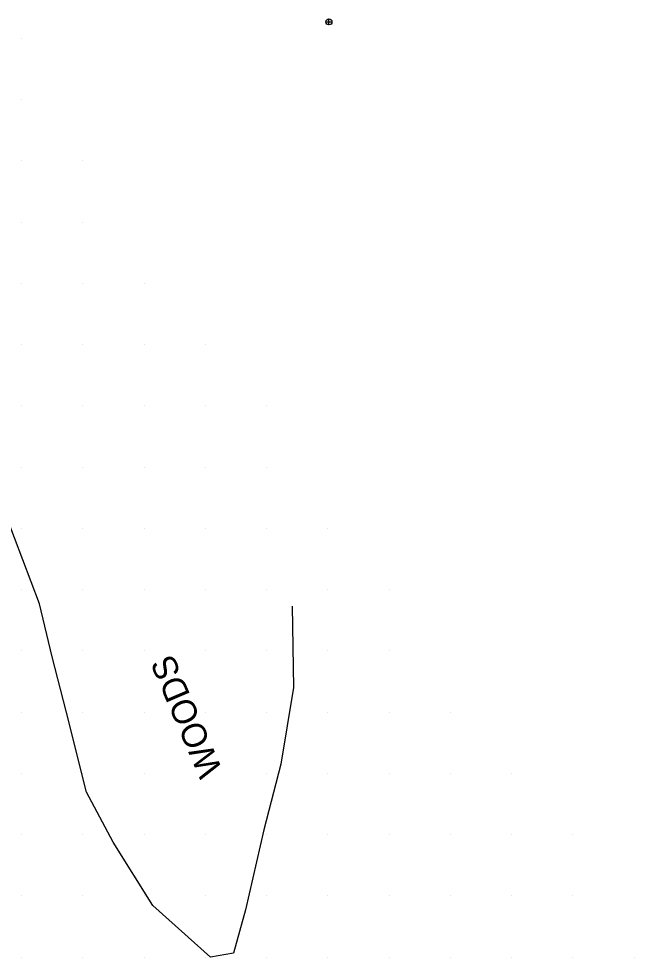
# Model space of a CAD drawing. Extents: x 1548934 to 1561348, y 809680 to 824075.
# Drawn here: x 1552269.6 to 1552370, y 810279.9 to 810433.2 of the extents above; entities that cross this region are included whole.
import ezdxf

# ---------------------------------------------------------------- set-up
doc = ezdxf.new("R2010")
doc.units = 0
for name, color, linetype in [('Default', 7, 'Continuous'), ('Exist DTM QL2 LIDAR Elevation Point', 7, 'Continuous'), ('Exist Vegetation Woods Line', 7, 'Continuous'), ('Exist Vegetation Woods Line Text', 7, 'Continuous')]:
    doc.layers.add(name, color=color, linetype=linetype)

# ---------------------------------------------------------------- blocks, each defined once
blk = doc.blocks.new('SurveyPointCell')
at = {"layer": 'Default'}
for p, q in [((-0.5, 0), (0.5, 0)), ((0, -0.5), (0, 0.5))]:
    blk.add_line(p, q, dxfattribs=at)
blk.add_circle((0, 0), 0.5, dxfattribs=at)

msp = doc.modelspace()

# ---------------------------------------------------------------- linework, layer by layer
at = {"layer": 'Exist DTM QL2 LIDAR Elevation Point'}
for p, q in [((1552270.04, 810429.97), (1552270.04, 810429.97)), ((1552270.04, 810419.96), (1552270.04, 810419.96)), ((1552270.04, 810409.96), (1552270.04, 810409.96)), ((1552280.04, 810409.96), (1552280.04, 810409.96)), ((1552270.04, 810399.96), (1552270.04, 810399.96)), ((1552280.04, 810399.96), (1552280.04, 810399.96)), ((1552270.04, 810389.96), (1552270.04, 810389.96)), ((1552280.04, 810389.96), (1552280.04, 810389.96)), ((1552290.04, 810389.96), (1552290.04, 810389.96)), ((1552270.04, 810379.96), (1552270.04, 810379.96)), ((1552280.04, 810379.96), (1552280.04, 810379.96)), ((1552290.04, 810379.96), (1552290.04, 810379.96)), ((1552300.04, 810379.96), (1552300.04, 810379.96)), ((1552270.04, 810369.96), (1552270.04, 810369.96)), ((1552280.04, 810369.96), (1552280.04, 810369.96)), ((1552290.04, 810369.96), (1552290.04, 810369.96)), ((1552300.04, 810369.96), (1552300.04, 810369.96)), ((1552310.04, 810369.96), (1552310.04, 810369.96)), ((1552270.04, 810359.96), (1552270.04, 810359.96)), ((1552280.04, 810359.96), (1552280.04, 810359.96)), ((1552290.04, 810359.96), (1552290.04, 810359.96)), ((1552300.04, 810359.96), (1552300.04, 810359.96)), ((1552310.04, 810359.96), (1552310.04, 810359.96)), ((1552270.04, 810349.96), (1552270.04, 810349.96)), ((1552280.04, 810349.96), (1552280.04, 810349.96)), ((1552290.04, 810349.96), (1552290.04, 810349.96)), ((1552300.04, 810349.96), (1552300.04, 810349.96)), ((1552310.04, 810349.96), (1552310.04, 810349.96)), ((1552320.04, 810349.96), (1552320.04, 810349.96)), ((1552270.04, 810339.96), (1552270.04, 810339.96)), ((1552280.04, 810339.96), (1552280.04, 810339.96)), ((1552290.04, 810339.96), (1552290.04, 810339.96)), ((1552300.04, 810339.96), (1552300.04, 810339.96)), ((1552310.04, 810339.96), (1552310.04, 810339.96)), ((1552320.04, 810339.96), (1552320.04, 810339.96)), ((1552330.05, 810339.96), (1552330.05, 810339.96)), ((1552270.04, 810329.96), (1552270.04, 810329.96)), ((1552280.04, 810329.96), (1552280.04, 810329.96)), ((1552290.04, 810329.96), (1552290.04, 810329.96)), ((1552300.04, 810329.96), (1552300.04, 810329.96)), ((1552310.04, 810329.96), (1552310.04, 810329.96)), ((1552320.04, 810329.96), (1552320.04, 810329.96)), ((1552330.05, 810329.96), (1552330.05, 810329.96)), ((1552270.04, 810319.96), (1552270.04, 810319.96)), ((1552280.04, 810319.96), (1552280.04, 810319.96)), ((1552290.04, 810319.96), (1552290.04, 810319.96)), ((1552300.04, 810319.96), (1552300.04, 810319.96)), ((1552310.04, 810319.96), (1552310.04, 810319.96)), ((1552320.04, 810319.96), (1552320.04, 810319.96)), ((1552330.05, 810319.96), (1552330.05, 810319.96)), ((1552340.05, 810319.96), (1552340.05, 810319.96)), ((1552270.04, 810309.96), (1552270.04, 810309.96)), ((1552280.04, 810309.96), (1552280.04, 810309.96)), ((1552290.04, 810309.96), (1552290.04, 810309.96)), ((1552300.04, 810309.96), (1552300.04, 810309.96)), ((1552310.04, 810309.96), (1552310.04, 810309.96)), ((1552320.04, 810309.96), (1552320.04, 810309.96)), ((1552330.05, 810309.96), (1552330.05, 810309.96)), ((1552340.05, 810309.96), (1552340.05, 810309.96)), ((1552350.05, 810309.96), (1552350.05, 810309.96)), ((1552270.04, 810299.96), (1552270.04, 810299.96)), ((1552280.04, 810299.96), (1552280.04, 810299.96)), ((1552290.04, 810299.96), (1552290.04, 810299.96)), ((1552300.04, 810299.96), (1552300.04, 810299.96)), ((1552310.04, 810299.96), (1552310.04, 810299.96)), ((1552320.04, 810299.96), (1552320.04, 810299.96)), ((1552330.05, 810299.96), (1552330.05, 810299.96)), ((1552340.05, 810299.96), (1552340.05, 810299.96)), ((1552350.05, 810299.96), (1552350.05, 810299.96)), ((1552360.05, 810299.96), (1552360.05, 810299.96)), ((1552270.04, 810289.95), (1552270.04, 810289.95)), ((1552280.04, 810289.95), (1552280.04, 810289.95)), ((1552290.04, 810289.95), (1552290.04, 810289.95)), ((1552300.04, 810289.95), (1552300.04, 810289.95)), ((1552310.04, 810289.95), (1552310.04, 810289.95)), ((1552320.04, 810289.95), (1552320.04, 810289.95)), ((1552330.05, 810289.95), (1552330.05, 810289.95)), ((1552340.05, 810289.95), (1552340.05, 810289.95)), ((1552350.05, 810289.95), (1552350.05, 810289.95)), ((1552360.05, 810289.95), (1552360.05, 810289.95)), ((1552270.04, 810279.95), (1552270.04, 810279.95)), ((1552280.04, 810279.95), (1552280.04, 810279.95)), ((1552290.04, 810279.95), (1552290.04, 810279.95)), ((1552300.04, 810279.95), (1552300.04, 810279.95)), ((1552310.04, 810279.95), (1552310.04, 810279.95)), ((1552320.04, 810279.95), (1552320.04, 810279.95)), ((1552330.05, 810279.95), (1552330.05, 810279.95)), ((1552340.05, 810279.95), (1552340.05, 810279.95)), ((1552350.05, 810279.95), (1552350.05, 810279.95)), ((1552360.05, 810279.95), (1552360.05, 810279.95)), ((1552370.05, 810279.95), (1552370.05, 810279.95))]:
    msp.add_line(p, q, dxfattribs=at)
at = {"layer": 'Exist Vegetation Woods Line'}
msp.add_lwpolyline([(1552314.23, 810337.27), (1552314.45, 810323.99), (1552312.34, 810311.44), (1552309.57, 810300.74), (1552306.59, 810287.71), (1552304.62, 810280.59), (1552300.86, 810279.95), (1552291.44, 810288.38), (1552284.97, 810298.73), (1552280.66, 810306.9), (1552277.34, 810320.11), (1552275.03, 810329), (1552272.99, 810337.64), (1552267.52, 810351.99), (1552264.38, 810361.28), (1552261.07, 810376.4), (1552260.02, 810389.55)], dxfattribs=at)

# ---------------------------------------------------------------- block references
at = {"layer": 'Default'}
msp.add_blockref('SurveyPointCell', (1552320.2, 810432.66), dxfattribs=at)

# ---------------------------------------------------------------- texts
at = {"layer": 'Exist Vegetation Woods Line Text'}
msp.add_text('WOODS', height=4.02, rotation=113.1736, dxfattribs=at).set_placement((1552302.91, 810310.39))

doc.saveas('drawing.dxf')
